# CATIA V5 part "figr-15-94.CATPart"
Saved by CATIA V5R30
Part number: Part1
Bounding box of the stored display mesh (mm): x -40 to 40, y -60 to 60, z -4 to 2
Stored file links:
  D:\PROJECTS\CATIA V56R 2020\Resources\Parts File\c15_catia_v5_6r2020_prt\figr-15-94.CATPart
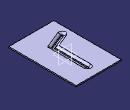
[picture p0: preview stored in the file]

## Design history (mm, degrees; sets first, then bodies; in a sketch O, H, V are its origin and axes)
SheetMetalParameters1: Thickness 2, BendRadius 4, KFactor 0.400515 {= log(min(100,max(20*SheetMetalParameters1.BendRadius,SheetMetalParameters1.Thickness)/SheetMetalParameters1.Thickness))/log(100)/2}, ReliefRadialLength 1, ReliefAxialLength 2, MinimumBendRadius 0
Body1 (main body)
  Sketch1 on xy-plane, origin (0, 0, 0), H (-1, 0, 0), V (0, -1, 0)
    line L1 (40, 60) -> (40, -60)
    line L2 (40, -60) -> (-40, -60)
    line L3 (-40, -60) -> (-40, 60)
    line L4 (-40, 60) -> (40, 60)
    length L4 = 80
    length L1 = 120
    vertical: L1 V, L3 V
    horizontal: L2 H, L4 H
    equidistance: L1 L3 O, L2 L4 O
  Wall1: Thickness 2, Profile Sketch1, OffsetValue 0
  Sketch2 on face of Wall1, origin (0, 0, 2), H (1, 0, 0), V (0, 1, 0)
    line L1 (0, 40.0798) -> (0, -21.0085)
    line L2 (0, -21.0085) -> (-27, -32)
    vertical: L1 V
  d_Stamp1: NewRoot_AttribNormalisation "No Standard", Stamp_FilletRadius 2, Stamp_IntersectFilletRadius 2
